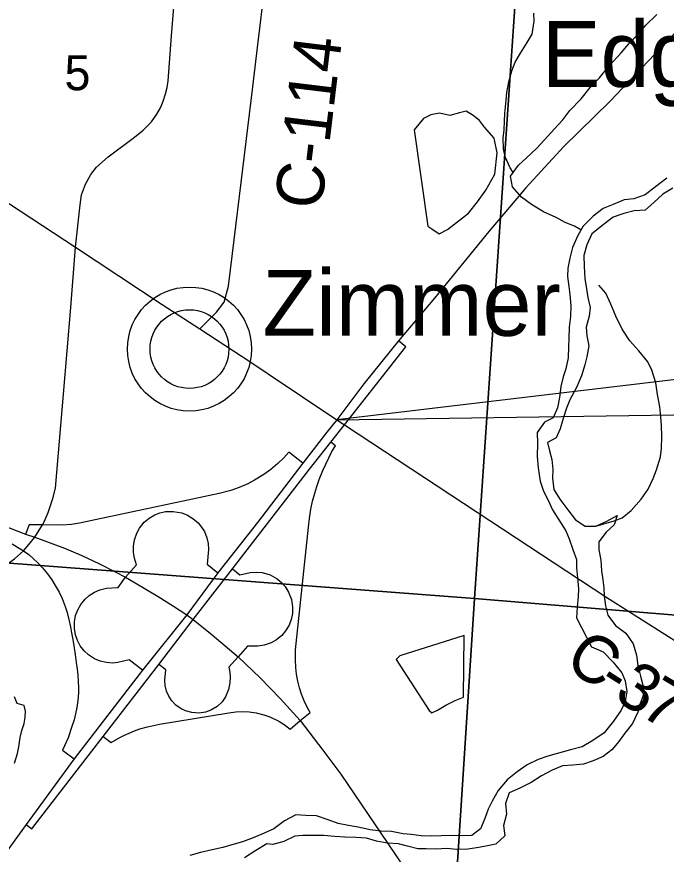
# Model space of a CAD drawing. Extents: x 0 to 34, y 0 to 22.
# Drawn here: x 5.595 to 6.374, y 16.825 to 17.828 of the extents above; entities that cross this region are included whole.
import ezdxf

# ---------------------------------------------------------------- set-up
doc = ezdxf.new("R2010")
doc.units = 0
for name, color, linetype in [('BD_P_Text', 7, 'Continuous'), ('GM_P_County_Alignment', 7, 'Continuous'), ('GM_X_City_Street', 7, 'Continuous'), ('GM_X_County_Road', 7, 'Continuous'), ('GM_X_County_Road_Text', 7, 'Continuous'), ('GM_X_Interchange_Ramps', 7, 'Continuous'), ('GM_X_Interstate_Route', 7, 'Continuous'), ('GM_X_Major_River', 7, 'Continuous'), ('GM_X_Minor_Lake', 7, 'Continuous'), ('GM_X_Minor_River', 7, 'Continuous'), ('GM_X_Section', 7, 'Continuous'), ('GM_X_Section_Text', 7, 'Continuous'), ('GM_X_Township_Road', 7, 'Continuous'), ('GM_X_Unincorporated', 7, 'Continuous'), ('GM_X_Unincorporated_Location', 7, 'Continuous'), ('GM_X_Unincorporated_Text', 7, 'Continuous'), ('GM_X_US_Route', 7, 'Continuous')]:
    doc.layers.add(name, color=color, linetype=linetype)

msp = doc.modelspace()

# ---------------------------------------------------------------- linework, layer by layer
at = {"layer": 'BD_P_Text'}
msp.add_lwpolyline([(9.7485, 17.7931), (5.9787, 17.3454), (9.7485, 17.4014)], close=True, dxfattribs=at)
at = {"layer": 'GM_P_County_Alignment'}
msp.add_lwpolyline([(5.6653, 17.5523), (5.6709, 17.6029), (5.6725, 17.615), (5.6774, 17.6277), (5.6838, 17.6393), (5.6906, 17.6481), (5.7044, 17.6606), (5.7361, 17.6842), (5.7466, 17.6924), (5.7565, 17.7026), (5.763, 17.7119), (5.7672, 17.7192), (5.7706, 17.7271), (5.7733, 17.7359), (5.7752, 17.7436), (5.7767, 17.7516), (5.7807, 17.8057), (5.7833, 17.8401), (5.8763, 18.1039)], dxfattribs=at)
at = {"layer": 'GM_X_City_Street'}
for points in [[(5.6289, 17.226), (5.6328, 17.2344), (5.6381, 17.2509), (5.6415, 17.2635)], [(5.5851, 17.1734), (5.5923, 17.1785), (5.603, 17.1882), (5.6115, 17.1981), (5.6165, 17.2048), (5.6259, 17.2193), (5.6277, 17.2232), (5.6289, 17.226)]]:
    msp.add_lwpolyline(points, dxfattribs=at)
at = {"layer": 'GM_X_County_Road'}
for points in [[(5.8147, 17.4543), (5.8345, 17.4743), (5.8435, 17.4864), (5.8488, 17.5055), (5.8535, 17.5445), (5.8659, 17.6463), (5.8781, 17.7446), (5.8838, 17.7918), (5.8929, 17.8681), (5.8953, 17.8752), (5.9009, 17.8803), (5.9082, 17.8821), (5.9288, 17.8815), (6.02, 17.8785), (6.0235, 17.8787), (6.0256, 17.8788), (6.0305, 17.8815), (6.0338, 17.8861), (6.0347, 17.8916), (6.0349, 17.8976), (6.035, 17.9429)], [(5.1496, 17.8918), (5.1573, 17.8838), (5.1678, 17.876), (5.3625, 17.7509), (5.6653, 17.5523), (5.7694, 17.4837), (5.8147, 17.4543), (5.8758, 17.4145), (5.8966, 17.4004), (5.9787, 17.3454), (5.9879, 17.3394), (6.1472, 17.2345), (6.3013, 17.1331), (6.3963, 17.0731), (6.4389, 17.0483), (6.4571, 17.0376), (6.4744, 17.0295), (6.5397, 17.0026), (6.5904, 16.9823)]]:
    msp.add_lwpolyline(points, dxfattribs=at)
at = {"layer": 'GM_X_Interchange_Ramps'}
for points in [[(5.6064, 16.86), (5.6131, 16.8549), (5.6986, 16.9656), (5.7653, 17.0521), (5.8065, 17.1058), (5.8536, 17.1665), (5.946, 17.2861), (5.9715, 17.3185), (5.9879, 17.3394), (6.0616, 17.433), (6.0526, 17.44)], [(5.9349, 16.9847), (5.9467, 16.9946), (5.9437, 16.9999), (5.9398, 17.0083), (5.9366, 17.0163), (5.9342, 17.024), (5.9322, 17.032), (5.9306, 17.0405), (5.9297, 17.0482), (5.9291, 17.0579), (5.9294, 17.0695), (5.9447, 17.2166), (5.9459, 17.2269), (5.9478, 17.2384), (5.9498, 17.2478), (5.9523, 17.2572), (5.9549, 17.2655), (5.9578, 17.2738), (5.9622, 17.2845), (5.9658, 17.2922), (5.973, 17.3073), (5.9771, 17.3141), (5.9715, 17.3185)], [(5.938, 17.2935), (5.9214, 17.3065), (5.9151, 17.2997), (5.9081, 17.2929), (5.8996, 17.2858), (5.8911, 17.2796), (5.8801, 17.2728), (5.8721, 17.2687), (5.8616, 17.2641), (5.8516, 17.2606), (5.8378, 17.257), (5.6701, 17.2214), (5.6605, 17.22), (5.649, 17.2191), (5.6259, 17.2193), (5.6099, 17.2194), (5.6056, 17.2084)], [(5.7255, 17.1565), (5.7385, 17.1713), (5.736, 17.1795), (5.7348, 17.1864), (5.7348, 17.1937), (5.736, 17.2014), (5.7388, 17.2095), (5.7422, 17.2154), (5.7479, 17.2225), (5.7537, 17.2274), (5.7604, 17.2313), (5.7666, 17.2337), (5.7734, 17.2353), (5.7825, 17.2356), (5.793, 17.2337), (5.7998, 17.2311), (5.8063, 17.2271), (5.8124, 17.2219), (5.8167, 17.2167), (5.82, 17.2113), (5.823, 17.2038), (5.8246, 17.1971), (5.825, 17.1899), (5.8232, 17.1722), (5.8362, 17.1618)], [(5.5894, 17.1965), (5.596, 17.1926), (5.603, 17.1882), (5.6094, 17.1837), (5.615, 17.1788), (5.6202, 17.1739), (5.6259, 17.1678), (5.6319, 17.1606), (5.637, 17.1535), (5.6412, 17.1468), (5.6458, 17.1386), (5.6493, 17.131), (5.653, 17.1216), (5.6553, 17.1144), (5.6575, 17.1059), (5.6594, 17.0972), (5.6608, 17.0901), (5.6623, 17.0818), (5.6639, 17.0721), (5.6652, 17.0638), (5.6664, 17.0545), (5.6673, 17.0466), (5.6681, 17.0398), (5.6688, 17.0318), (5.6691, 17.0243), (5.6689, 17.018), (5.6683, 17.009), (5.6671, 17.0006), (5.6656, 16.9929), (5.6637, 16.9856), (5.6612, 16.9776), (5.6565, 16.9641), (5.65, 16.9494), (5.664, 16.9391)], [(5.8536, 17.1665), (5.8626, 17.1593), (5.8748, 17.1623), (5.8821, 17.1628), (5.8893, 17.1621), (5.8988, 17.1593), (5.9073, 17.1545), (5.9123, 17.1504), (5.9167, 17.1455), (5.921, 17.1386), (5.9244, 17.13), (5.9258, 17.1212), (5.9256, 17.1132), (5.9242, 17.106), (5.9215, 17.099), (5.9174, 17.0922), (5.9129, 17.0869), (5.9065, 17.0815), (5.9001, 17.0779), (5.8916, 17.075), (5.8839, 17.0739), (5.8715, 17.074), (5.8606, 17.0611)], [(5.7459, 17.0453), (5.7297, 17.0576), (5.716, 17.0542), (5.7097, 17.0537), (5.7026, 17.0542), (5.695, 17.056), (5.6881, 17.0589), (5.6808, 17.0637), (5.6759, 17.0683), (5.6712, 17.0744), (5.6677, 17.0808), (5.6654, 17.0876), (5.6641, 17.0952), (5.6642, 17.1032), (5.6656, 17.1108), (5.6682, 17.1177), (5.6718, 17.1241), (5.6768, 17.1302), (5.6819, 17.1348), (5.688, 17.1386), (5.6945, 17.1414), (5.7025, 17.1434), (5.7166, 17.1442), (5.7255, 17.1565)], [(5.8606, 17.0611), (5.8494, 17.0489), (5.8503, 17.043), (5.8508, 17.0367), (5.8504, 17.0302), (5.849, 17.0222), (5.8452, 17.0132), (5.8411, 17.0074), (5.8352, 17.0018), (5.8279, 16.9974), (5.8214, 16.995), (5.8138, 16.9938), (5.8051, 16.9943), (5.7973, 16.9964), (5.7923, 16.9988), (5.7858, 17.0034), (5.7809, 17.0085), (5.7772, 17.0141), (5.7746, 17.02), (5.7729, 17.0267), (5.7724, 17.0334), (5.7736, 17.0458), (5.7653, 17.0521)], [(5.6986, 16.9656), (5.708, 16.9584), (5.7185, 16.9643), (5.7243, 16.9673), (5.7296, 16.9697), (5.7363, 16.9725), (5.7425, 16.9747), (5.7516, 16.9773), (5.7663, 16.9806), (5.8493, 16.9942), (5.8577, 16.9953), (5.8662, 16.9956), (5.8736, 16.9951), (5.882, 16.9939), (5.8912, 16.9916), (5.8984, 16.9891), (5.9091, 16.984), (5.9156, 16.9799), (5.9227, 16.9746), (5.9349, 16.9847)]]:
    msp.add_lwpolyline(points, dxfattribs=at)
at = {"layer": 'GM_X_Interstate_Route'}
for points in [[(6.6338, 18.046), (6.5392, 17.957), (6.4517, 17.8729), (6.3828, 17.8077), (6.3064, 17.727), (6.2509, 17.6728), (6.2053, 17.6234), (6.1901, 17.6054)], [(6.1901, 17.6054), (6.1611, 17.5711), (6.0959, 17.4913), (6.0526, 17.44)], [(6.0526, 17.44), (6.0112, 17.3886), (5.9787, 17.3454), (5.967, 17.3306)], [(5.967, 17.3306), (5.938, 17.2935), (5.8838, 17.2222), (5.8362, 17.1618), (5.799, 17.1116)], [(5.799, 17.1116), (5.7459, 17.0453), (5.664, 16.9391), (5.6064, 16.86)], [(5.6064, 16.86), (5.5612, 16.7983), (5.4292, 16.6277), (5.3235, 16.4867), (5.1841, 16.3077), (5.0901, 16.1822)]]:
    msp.add_lwpolyline(points, dxfattribs=at)
at = {"layer": 'GM_X_Major_River'}
msp.add_line((6.2661, 17.1079), (6.2843, 17.0731), dxfattribs=at)
for points in [[(6.3745, 17.6351), (6.3609, 17.6245), (6.3484, 17.615), (6.3351, 17.6101), (6.3234, 17.6089), (6.3101, 17.6036), (6.2984, 17.5987), (6.2863, 17.5896), (6.2741, 17.5774), (6.2677, 17.5661), (6.2616, 17.552), (6.2582, 17.5391), (6.256, 17.527), (6.2556, 17.5171), (6.2571, 17.505), (6.2582, 17.4955), (6.2594, 17.4819), (6.259, 17.469), (6.2575, 17.4564), (6.2571, 17.4432), (6.2567, 17.4329), (6.2563, 17.4197), (6.2533, 17.4064), (6.2503, 17.3969), (6.2476, 17.3851), (6.2457, 17.3719), (6.2434, 17.3597), (6.2381, 17.3476), (6.2279, 17.3423), (6.2192, 17.3301), (6.2196, 17.3169), (6.2192, 17.3013), (6.2203, 17.2877), (6.2226, 17.2717)], [(6.3817, 17.623), (6.3696, 17.6158), (6.359, 17.6059), (6.3487, 17.5968), (6.3355, 17.5957), (6.323, 17.5926), (6.3101, 17.5881), (6.2984, 17.579), (6.2847, 17.5683), (6.2787, 17.5551), (6.2749, 17.5422), (6.2753, 17.5293), (6.2764, 17.5149), (6.2783, 17.5023), (6.2798, 17.4921), (6.2828, 17.48), (6.2813, 17.4694), (6.2779, 17.4565), (6.2787, 17.4458), (6.2809, 17.4341), (6.2787, 17.4208), (6.2764, 17.4113), (6.2722, 17.3981), (6.2662, 17.384), (6.2582, 17.3692), (6.2544, 17.3594), (6.2502, 17.3468), (6.2465, 17.3347), (6.2419, 17.3237), (6.2313, 17.318), (6.234, 17.3082), (6.2366, 17.2979), (6.2377, 17.2858), (6.2374, 17.2755), (6.2392, 17.2619), (6.2464, 17.2501), (6.2559, 17.2373), (6.265, 17.2255), (6.2767, 17.2179), (6.2896, 17.2179)], [(6.2226, 17.2717), (6.2267, 17.2596), (6.2317, 17.2498), (6.2373, 17.2376), (6.2449, 17.2255), (6.2536, 17.2122), (6.2574, 17.2027), (6.2619, 17.1899), (6.2661, 17.1777), (6.2661, 17.1679), (6.2676, 17.1557), (6.2688, 17.1428), (6.2684, 17.1334), (6.2672, 17.1208), (6.2661, 17.1079)], [(6.2896, 17.2179), (6.3028, 17.224), (6.315, 17.2305), (6.3116, 17.2195), (6.3017, 17.2107), (6.293, 17.199), (6.293, 17.1895), (6.2953, 17.177), (6.2964, 17.1641), (6.2979, 17.1535), (6.299, 17.144), (6.2994, 17.1341), (6.3009, 17.1224), (6.304, 17.111), (6.313, 17.0989), (6.3255, 17.0894), (6.3342, 17.0769), (6.3384, 17.0632), (6.3399, 17.0507), (6.3429, 17.0382), (6.3456, 17.0272), (6.3463, 17.0147), (6.3426, 17.0052), (6.3399, 16.995), (6.3335, 16.9813), (6.3244, 16.9696), (6.3172, 16.9597), (6.3088, 16.9498), (6.2982, 16.9419), (6.2861, 16.9365), (6.2748, 16.9324), (6.2619, 16.9312), (6.2494, 16.9305), (6.2369, 16.9255), (6.2244, 16.9187), (6.2119, 16.9107), (6.1983, 16.9039), (6.1854, 16.8982), (6.1812, 16.8853), (6.1824, 16.8724), (6.1786, 16.8591), (6.1801, 16.8466), (6.1695, 16.8367), (6.1596, 16.8345), (6.149, 16.8326), (6.1358, 16.8307), (6.1229, 16.8303), (6.1108, 16.8314), (6.0979, 16.8306), (6.0858, 16.831), (6.076, 16.831), (6.0635, 16.8344), (6.0529, 16.8371), (6.0396, 16.8378), (6.0264, 16.8401), (6.0142, 16.8439), (6.0018, 16.8446), (5.9885, 16.845), (5.976, 16.8457), (5.9631, 16.8469), (5.9506, 16.8472), (5.9381, 16.8472), (5.9283, 16.8461), (5.9154, 16.84), (5.9022, 16.8362)], [(6.2843, 17.0731), (6.2983, 17.067), (6.3104, 17.0549), (6.3206, 17.042), (6.3248, 17.0325), (6.3267, 17.0196), (6.3248, 17.0075), (6.3198, 16.9972), (6.3107, 16.984), (6.2994, 16.9699), (6.2858, 16.9608), (6.2729, 16.9532), (6.2592, 16.9498), (6.232, 16.9422), (6.2202, 16.938), (6.207, 16.9319), (6.1949, 16.9232), (6.1831, 16.9137), (6.1722, 16.9008), (6.165, 16.8883), (6.1604, 16.8785), (6.1562, 16.8675), (6.1513, 16.8549), (6.1407, 16.847), (6.1286, 16.8466), (6.1161, 16.8469), (6.104, 16.8466), (6.0922, 16.8462), (6.0798, 16.8465), (6.068, 16.8481), (6.0582, 16.8492), (6.0445, 16.8518), (6.0317, 16.8522), (6.0188, 16.8537), (6.0063, 16.8567), (5.9927, 16.859), (5.9806, 16.8613), (5.9684, 16.8658), (5.9544, 16.8704), (5.9416, 16.8711), (5.9298, 16.8719), (5.9162, 16.8647), (5.9033, 16.8548), (5.8916, 16.8499), (5.8783, 16.8442), (5.8658, 16.8396), (5.8529, 16.8358), (5.842, 16.8328), (5.8295, 16.8297), (5.8155, 16.8267), (5.8026, 16.8229)], [(5.9022, 16.8362), (5.895, 16.837), (5.8817, 16.829), (5.8681, 16.8203)]]:
    msp.add_lwpolyline(points, dxfattribs=at)
at = {"layer": 'GM_X_Minor_Lake'}
for points in [[(6.0879, 17.5776), (6.0927, 17.5742), (6.1014, 17.5684), (6.1117, 17.5733), (6.1368, 17.5932), (6.1476, 17.6067), (6.1576, 17.6207), (6.1683, 17.6396), (6.1712, 17.6654), (6.1676, 17.6828), (6.156, 17.6962), (6.15, 17.7042), (6.1425, 17.71), (6.1338, 17.7154), (6.1259, 17.7132), (6.1145, 17.7102), (6.102, 17.713), (6.0914, 17.7108), (6.0826, 17.7067), (6.0715, 17.6931)], [(6.0715, 17.6931), (6.0879, 17.5776)], [(6.1316, 17.0866), (6.0542, 17.0622), (6.05, 17.0581), (6.0895, 16.9967), (6.0929, 16.994), (6.0994, 16.9974), (6.1097, 17.0033), (6.1207, 17.0089), (6.1306, 17.013)], [(6.1306, 17.013), (6.1316, 17.0866)], [(5.5922, 16.9336), (5.5957, 16.9453), (5.5976, 16.9532), (5.5989, 16.9646), (5.6009, 16.9729), (5.604, 16.9813), (5.6052, 16.9885), (5.6056, 16.9961), (5.6038, 17.0029), (5.5955, 17.0052), (5.5922, 17.0132)]]:
    msp.add_lwpolyline(points, dxfattribs=at)
at = {"layer": 'GM_X_Minor_River'}
for points in [[(6.1902, 17.6419), (6.1866, 17.6474), (6.1806, 17.6604), (6.1788, 17.6702), (6.1782, 17.6831), (6.1794, 17.693), (6.1799, 17.7032), (6.1804, 17.7127), (6.1817, 17.7283), (6.1825, 17.7378), (6.1849, 17.7506), (6.1888, 17.7635), (6.1927, 17.7741), (6.1992, 17.7847), (6.2069, 17.7975), (6.2131, 17.8077), (6.2155, 17.8232), (6.2152, 17.8327)], [(6.2716, 17.573), (6.2639, 17.5773), (6.2526, 17.582), (6.2417, 17.5878), (6.2266, 17.5947), (6.2123, 17.6036), (6.2003, 17.6124), (6.1894, 17.6246), (6.1869, 17.6375), (6.1965, 17.6504), (6.206, 17.659), (6.2186, 17.671), (6.2278, 17.6808), (6.2397, 17.694), (6.25, 17.7049), (6.2584, 17.7163), (6.2718, 17.7302), (6.2825, 17.7438), (6.294, 17.7554), (6.3055, 17.7698), (6.32, 17.7852), (6.3292, 17.7961), (6.3392, 17.8067), (6.3495, 17.8184), (6.3625, 17.8311)], [(6.2896, 17.2179), (6.3113, 17.2244), (6.3212, 17.2278), (6.3319, 17.2368), (6.3437, 17.25), (6.3522, 17.262), (6.3583, 17.2749), (6.3622, 17.2855), (6.3669, 17.301), (6.3682, 17.3109), (6.3687, 17.3253), (6.368, 17.3386), (6.3674, 17.3488), (6.366, 17.361), (6.3635, 17.3758), (6.3613, 17.3898), (6.3565, 17.4047), (6.3517, 17.415), (6.3409, 17.428), (6.3304, 17.4398), (6.321, 17.4539), (6.3136, 17.4695), (6.3073, 17.484), (6.3014, 17.4973), (6.2932, 17.5069)]]:
    msp.add_lwpolyline(points, dxfattribs=at)
at = {"layer": 'GM_X_Section'}
for points in [[(5.1885, 18.1592), (5.2507, 18.1559), (5.7484, 18.1169), (6.2087, 18.0808), (6.1439, 17.131), (5.123, 17.2087)], [(6.2087, 18.0808), (6.2447, 18.0791), (6.7511, 18.0375), (7.2561, 17.997), (7.1918, 17.0445), (6.1439, 17.131)], [(5.123, 17.2087), (6.1439, 17.131), (6.0779, 16.1089), (5.0408, 16.1927)], [(6.1439, 17.131), (7.1918, 17.0445), (7.1133, 16.022), (6.0779, 16.1089)]]:
    msp.add_lwpolyline(points, close=True, dxfattribs=at)
at = {"layer": 'GM_X_Township_Road'}
msp.add_lwpolyline([(5.6415, 17.2635), (5.6511, 17.3762), (5.6597, 17.4801), (5.6653, 17.5523)], dxfattribs=at)
at = {"layer": 'GM_X_Unincorporated'}
for radius in [0.0744, 0.0472]:
    msp.add_circle((5.8021, 17.4301), radius, dxfattribs=at)
at = {"layer": 'GM_X_Unincorporated_Location'}
msp.add_line((5.8021, 17.4301), (5.8021, 17.4301), dxfattribs=at)
at = {"layer": 'GM_X_US_Route'}
for points in [[(5.578, 17.2191), (5.6056, 17.2084), (5.6165, 17.2048), (5.6523, 17.1916), (5.673, 17.1828), (5.6943, 17.1727), (5.7128, 17.1632), (5.7255, 17.1565), (5.737, 17.1497), (5.7646, 17.1334), (5.7828, 17.1218)], [(5.7828, 17.1218), (5.799, 17.1116), (5.8065, 17.1058), (5.8292, 17.0876), (5.8606, 17.0611), (5.8869, 17.0362), (5.9107, 17.0113), (5.9349, 16.9847), (5.962, 16.9493), (5.9836, 16.9207), (6.04, 16.8375), (6.1033, 16.7438), (6.1634, 16.657), (6.2001, 16.6111), (6.2389, 16.5659), (6.2721, 16.5311), (6.3142, 16.4908), (6.4672, 16.3597), (6.4747, 16.3532), (6.5753, 16.267), (6.6092, 16.2373)]]:
    msp.add_lwpolyline(points, dxfattribs=at)

# ---------------------------------------------------------------- texts
at = {"layer": 'GM_X_County_Road_Text'}
for s, height, rotation, p in [('C-114', 0.05682, 83.1099, (5.9603, 17.5962)), ('C', 0.0568, 327.2929, (6.2496, 17.0497)), ('3', 0.0568, 328.1431, (6.3093, 17.0115)), ('-', 0.0568, 327.5092, (6.2891, 17.0244)), ('7', 0.0568, 329.1352, (6.34, 16.9924))]:
    msp.add_text(s, height=height, rotation=rotation, dxfattribs=at).set_placement(p)
at = {"layer": 'GM_X_Section_Text'}
msp.add_text('5', height=0.0419, rotation=0, dxfattribs=at).set_placement((5.6522, 17.7404))
at = {"layer": 'GM_X_Unincorporated_Text'}
for s, p in [('Edgewater', (6.2246, 17.7444)), ('Zimmer', (5.8896, 17.446))]:
    msp.add_text(s, height=0.07898, rotation=0, dxfattribs=at).set_placement(p)

doc.saveas('drawing.dxf')
